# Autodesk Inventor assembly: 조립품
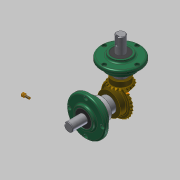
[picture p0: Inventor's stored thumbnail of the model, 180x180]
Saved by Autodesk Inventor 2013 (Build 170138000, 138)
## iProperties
Created: 2016-09
Part Number: 조립품
Document SubType Name: Assembly
Designer: Administrator
Author: Administrator
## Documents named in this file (14)
- C:\Users\Administrator\Documents\Inventor\460907V1001\조립품.iam
- C:\Users\Administrator\Documents\Inventor\460907V1001\본체.ipt
- C:\Users\Administrator\Documents\Inventor\460907V1001\460907V1001\M4.ipt
- C:\Users\Administrator\Documents\Inventor\460907V1001\460907V1001\메인 베벨기어.ipt
- C:\Users\Administrator\Documents\Inventor\460907V1001\460907V1001\메인 축.ipt
- 메인 축.ipt
- C:\Users\Administrator\Documents\Inventor\460907V1001\460907V1001\베어링 6203.ipt
- C:\Users\Administrator\Documents\Inventor\460907V1001\460907V1001\서브 베벨기어.ipt
- C:\Users\Administrator\Documents\Inventor\460907V1001\460907V1001\서브 축.ipt
- 서브 축.ipt
- C:\Users\Administrator\Documents\Inventor\460907V1001\460907V1001\오일실 17 32 8.ipt
- C:\Users\Administrator\Documents\Inventor\460907V1001\460907V1001\커버.ipt
- C:\Users\Administrator\Documents\Inventor\460907V1001\460907V1001\키 4x4.ipt
- C:\Users\Administrator\Documents\Inventor\460907V1001\460907V1001\키 5x5.ipt
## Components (1 placed, 1 different names)
1. M4:1
